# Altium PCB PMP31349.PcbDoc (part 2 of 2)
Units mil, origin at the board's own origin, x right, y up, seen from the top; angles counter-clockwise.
Board outline 2490.35 x 2400.55 mil, 4 copper layers (Top Layer, Internal Layer 1, Internal Layer 2, Bottom Layer), stack 73.068 mil thick; 110 components, 35 nets, 244 pads, 375 vias.
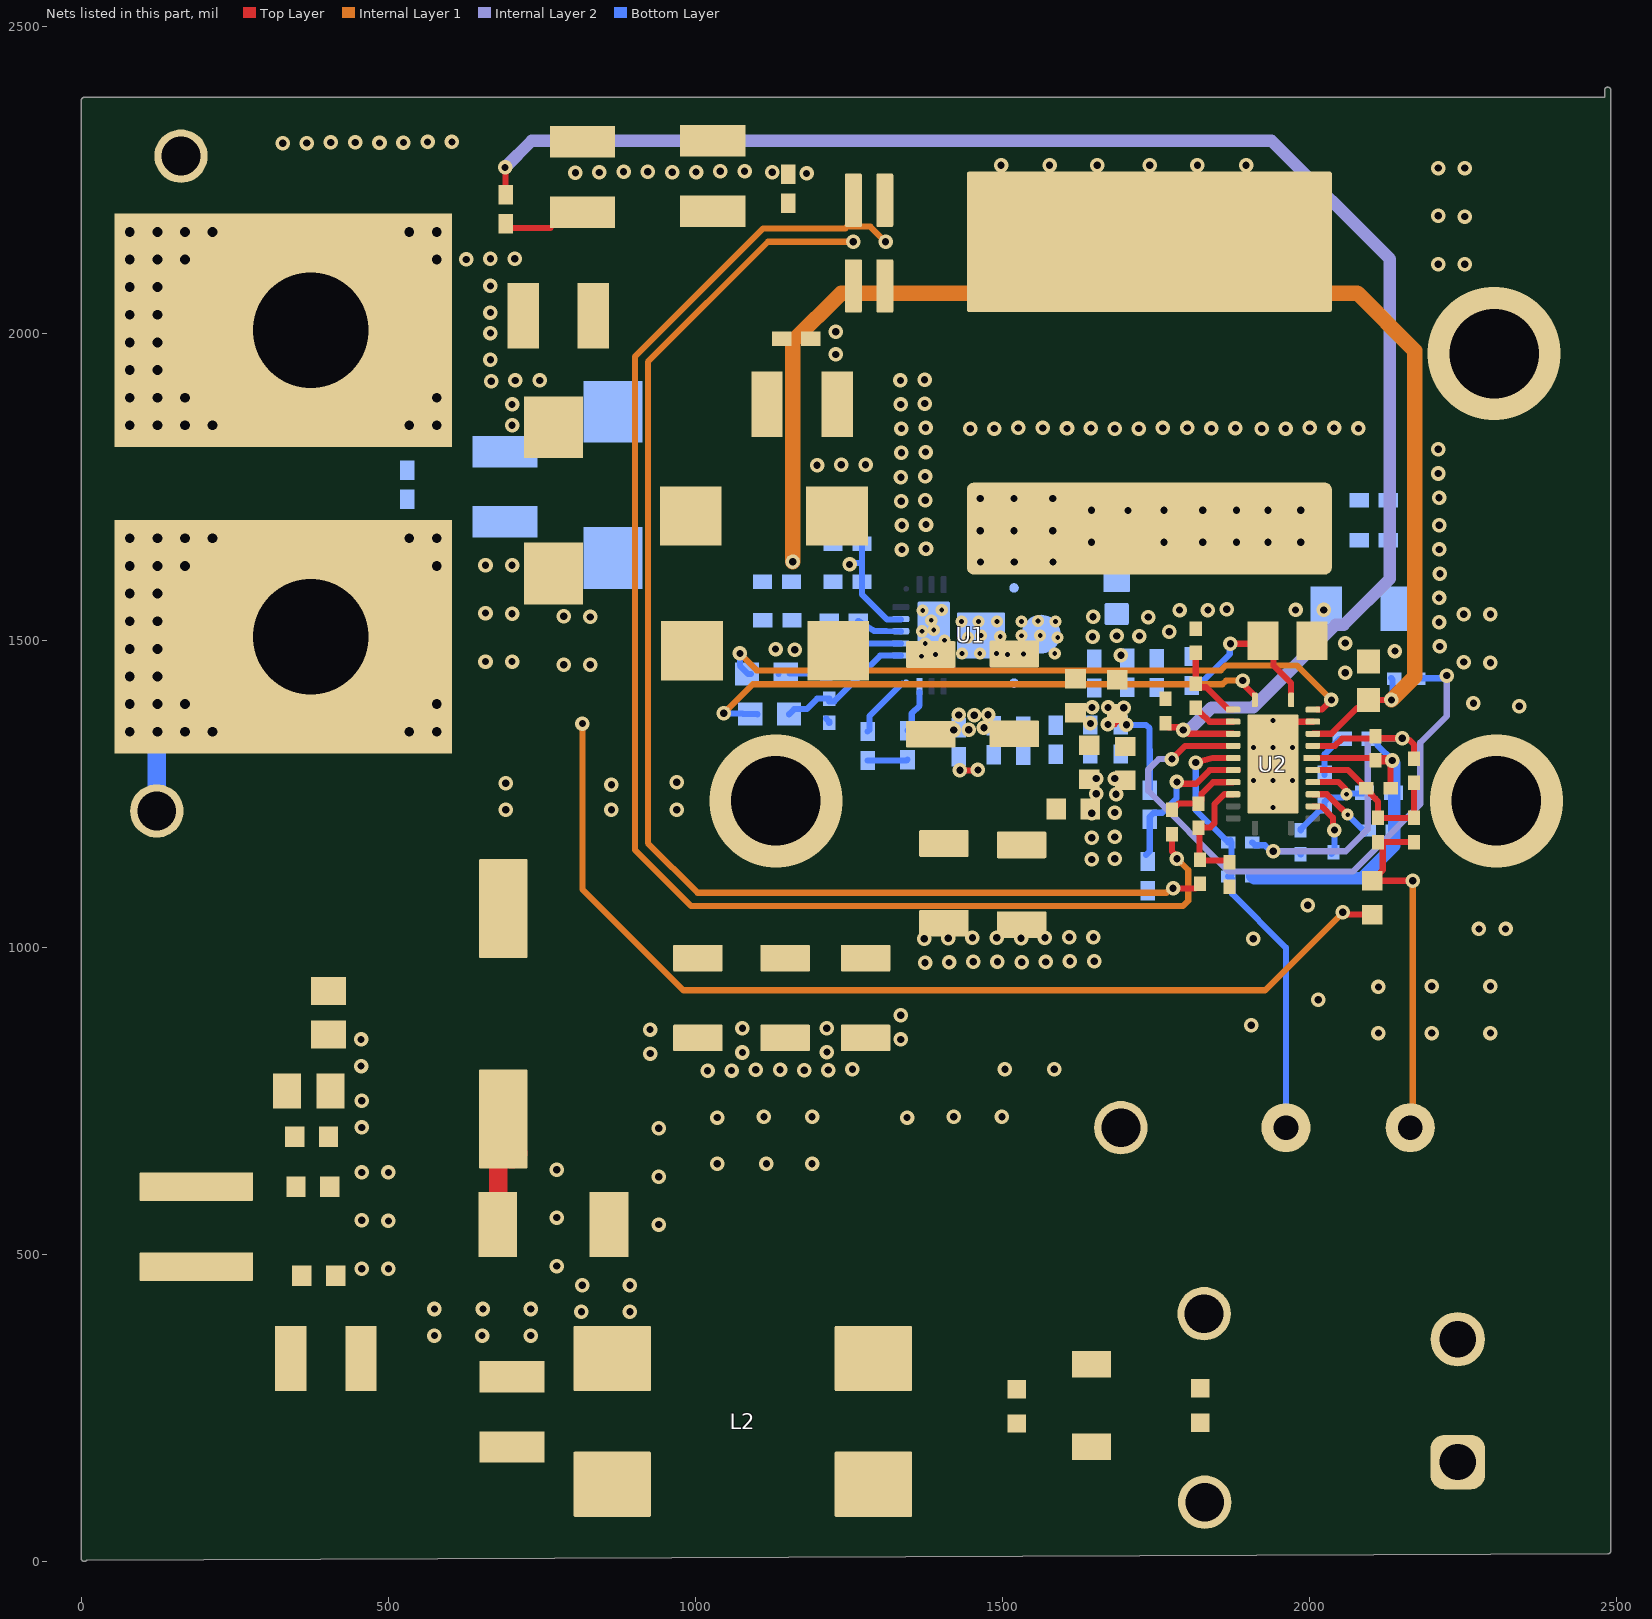
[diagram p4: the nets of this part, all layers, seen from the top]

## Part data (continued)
R22: library part CMP-0026403-2, "RES, 49.9 k, 1%, 0.063 W, AEC-Q200 Grade 0, 0402", Manufacturer=Vishay-Dale, Power_W=63mW, Supplier Part Number 1=541-49.9KLCT-ND, TempCo="100 ppm/C", Tolerance_%=1%, Value2=0.063W, Value_Code=49k9, ValueDisplayed=49.9k
R23: library part CMP-0025959-3, "RES, 10.2 k, 1%, 0.063 W, AEC-Q200 Grade 0, 0402", Manufacturer=Vishay-Dale, Power_W=63mW, Supplier Part Number 1=541-10.2KLCT-ND, TempCo="100 ppm/C", Tolerance_%=1%, Value2=0.063W, Value_Code=10k2, ValueDisplayed=10.2k
R24: library part CMP-0026225-2, "RES, 29.4 k, 1%, 0.063 W, AEC-Q200 Grade 0, 0402", Manufacturer=Vishay-Dale, Power_W=63mW, Supplier Part Number 1=541-29.4KLCT-ND, TempCo="100 ppm/C", Tolerance_%=1%, Value2=0.063W, Value_Code=29k4, ValueDisplayed=29.4k
R25: library part CMP-0026553-2, "RES, 7.15 k, 1%, 0.063 W, AEC-Q200 Grade 0, 0402", Manufacturer=Vishay-Dale, Power_W=63mW, Supplier Part Number 1=541-7.15KLCT-ND, TempCo="100 ppm/C", Tolerance_%=1%, Value2=0.063W, Value_Code=7k15, ValueDisplayed=DNP
U1: library part CMP-0120692-1, "100-V, 53-A GaN Half-Bridge Power Stage", Manufacturer="Texas Instruments", Max Supply Voltage=5.25V, Min Supply Voltage=4.75V, Nominal Supply Current=12mA, Operating Temperature Range="-40°C to +125°C"
U2: library part CMP-0049938-1, "Automotive, 80-V synchronous buck DC/DC controller with ultra-low IQ 24-VQFN -40 to 125", Digikey Part Number=296-LM5148QRGYRQ1CT-ND, Manufacturer="Texas Instruments", Max Supply Voltage=80V, Min Supply Voltage=3.5V, Mouser Part Number=595-LM5148QRGYRQ1, Nominal Supply Current=9.5-124uA, Operating Temperature Range="-40°C to +125°C", Output Voltage=3.3/5/12/0.8-55V, Switching Frequency=0.1-2.2MHz
Vin_Main VOUT: library part CMP-0055147-1, "Test Point, Multipurpose, Red, TH", Color=Red, Manufacturer=Keystone, PartNumber=5010, Supplier Part Number 1=36-5010-ND

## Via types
v1: diameter 23.62, hole 11.81, Top Layer to Bottom Layer, 274 vias
v2: diameter 32, hole 16, Top Layer to Bottom Layer, 56 vias
v3: diameter 19.68, hole 7.87, Top Layer to Bottom Layer, tented top, 26 vias
v4: diameter 19.68, hole 7.87, Top Layer to Bottom Layer, tented both sides, 11 vias
v5: diameter 23.62, hole 11.81, Top Layer to Bottom Layer, tented both sides, 5 vias
v6: diameter 216.54, hole 145.67, Top Layer to Bottom Layer, 3 vias

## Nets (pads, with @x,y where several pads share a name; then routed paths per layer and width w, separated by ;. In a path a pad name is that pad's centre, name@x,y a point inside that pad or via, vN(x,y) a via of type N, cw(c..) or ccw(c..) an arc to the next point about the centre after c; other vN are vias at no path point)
+Filter: C5.2 C6.2 C7.1 L1.2 L2.4
+Vin_Main: C2.1 C3.1 C4.1 J1.1 L2.1 Vin_Main.1
AGND1: C42.1 C56.2 C57.2 NT1.2 R18.2 R20.2 R24.2 R25.1 U2.7 | length 646.2
  Top Layer w10: U2.7@2005.53,1308.83 2107.23,1308.83 2107.23,1308.38 2109.02,1306.59 2112.07,1303.53 2126.21,1303.53 v1@2128.13,1301.62 ; R25.1@2131.92,1257.44 R25.1@2131.92,1259.62 v1@2131.92,1301.38
  Top Layer w15: C42.1@2107.23,1306.59 2109.02,1306.59 2130.37,1306.59 2132.21,1304.75 v1(2134.54,1304.75)
  Bottom Layer w10: C57.2@2100.31,1339.85 2104.25,1339.85 2111.06,1333.04 2111.06,1329.11 2134.54,1305.62 v1(2134.54,1304.75) v1@2137.15,1302.14
  Bottom Layer w20: R20.2@1906.7,1116.12 1910.09,1112.72 1953.69,1112.67 1977.25,1112.86 ; 1977.61,1112.49 2024.54,1112.86 2039.07,1112.86 2084.86,1112.86 2137.78,1165.77 2137.78,1252.58 2137.78,1300.53 2135.24,1303.08 v1@2135.73,1303.57
Bode: BODE.1 C55.1 R17.1 R21.2 | length 608
  Top Layer w10: R21.2@2111.71,1171.8 2119.25,1171.8 2138.74,1171.8 C55.1@2165.77,1171.8 ; R21.2@2119.25,1170.75 2119.25,1126.27 2113.63,1120.65 2113.63,1119.66 2102.88,1108.91 R17.1@2101.9,1108.91 2103.95,1108.91 v1(2168.05,1108.91) ; BODE.1@2154.81,716.23 ccw(c2164.12,716.23) BODE.1@2164.12,706.92
  Internal Layer 1 w10: BODE.1@2164.12,706.92 2168.05,710.86 v1(2168.05,1108.91)
CNFG: R24.1 U2.3 | length 102.8
  Top Layer w10: U2.3@2005.53,1230.09 2005.61,1230.01 2019.71,1230.01 2038.08,1211.64 2038.08,1194.14 v1(2040.69,1191.53)
  Bottom Layer w10: R24.1@2035.65,1152.23 2040.69,1157.27 v1(2040.69,1191.53)
COMP: C56.1 R19.1 R23.2 U2.5 | length 202.1
  Top Layer w10: U2.5@2005.53,1269.46 2047.44,1269.46 2058.48,1258.42 2058.48,1251.67 v3(2060.33,1249.82)
  Bottom Layer w10: R19.1@1985.68,1191.18 1985.68,1193.15 2015.6,1223.07 2017.73,1223.07 2024.54,1229.88 R23.2@2024.54,1233.82 2024.54,1237.75 2031.35,1244.56 2055.08,1244.56 2061.71,1251.2 2088.26,1251.2 C56.1@2089.64,1252.58
EN1: R4.1 R11.2 U2.19 | length 262.6
  Top Layer w10: v5(1784.2,1269.79) 1787.89,1269.79 1790.72,1266.96 1815.25,1266.96 1837.44,1289.14 U2.19@1883.44,1289.14
  Bottom Layer w10: R11.2@1733.97,1151.3 1739.82,1157.16 R4.1@1739.82,1203.13 ; R4.1@1739.82,1208.9 R4.1@1739.82,1203.13 ; v5(1784.2,1269.79) 1783.57,1269.16 1783.57,1242.98 1760.23,1219.64 1746.64,1219.64 1739.82,1212.83 R4.1@1739.82,1203.13
FB: C55.2 R21.1 R22.1 R25.2 U2.6 | length 274.2
  Top Layer w10: U2.6@2012.34,1289.07 2062.89,1289.07 2085.73,1266.22 2085.73,1262.28 2090.58,1257.44 2094.51,1257.44 2099.36,1252.6 2099.36,1250.63 2107.23,1242.75 2107.23,1242.26 2111.71,1237.78 R21.1@2111.71,1207.68 ; R21.1@2111.71,1211.17 2164.2,1211.17 C55.2@2169.86,1211.17 ; C55.2@2164.2,1209.15 2170.06,1215.01 R22.1@2170.06,1268.31
GND: C5.1 C6.1 C7.2 C8.2 C9.2 C10.2 C11.2 C12.2 C13.2 C14.2 C15.2 C16.2 C17.1 C18.1 C19.1 C20.1 C21.1 C22.1 C23.1 C24.2 C25.1 C26.1 C27.1 C28.2 C29.1 C30.1 C31.1 C32.1 C33.1 C34.1 C35.1 C36.1 C37.1 C38.2 C41.1 C43.2 C44.2 C45.2 C48.2 C49.2 C50.2 C51.2 C52.2 C53.2 C58.1 C59.2 C60.2 C61.2 C62.2 C63.2 C64.2 D1.2 GND.1 L2.3 NT1.1 R1.1 R8.2 R11.1 R15.1 TP7.1 U1.6 U1.15 U2.10 U2.25 | length 289.5
  Top Layer w10: v5(1430.8,1288.67) 1459.39,1288.67 ccw(c1459.39,1289.45) v1(1460.17,1289.45) ; v4(1940.57,1369.85) 1942.54,1367.88 U2.10@2005.53,1367.88
  Bottom Layer w10: C41.1@1213.28,1372.91 1218.12,1368.06 C41.1@1218.12,1366.1 ; v5(1251.09,1623.9) 1253.69,1626.51 1268.51,1626.51 1271.34,1629.34 ; C36.1@1271.34,1657.82 1271.34,1629.34 ; U1.15@1334.55,1534.56 1312.09,1534.56 1271.34,1575.31 C37.1@1271.34,1595.57 1271.34,1629.34
  other v1: 575.22,368.39 652.86,368.39 731.97,368.39 814.53,407.12 893.63,407.12 575.22,411.71 654.17,411.71 731.97,411.71 815.83,450.43 893.63,450.43 456.99,477.37 500.3,477.37 774.29,481.57 940.34,549.21 500.3,555.01 456.99,556.32 774.29,560.52 940.34,626.86 456.99,634.11 500.3,634.11 774.29,638.32 1035.59,648.28 1115.85,648.28 1190.04,648.28 940.34,705.96 456.99,707.33 1035.59,723.46 1344.81,723.46 1111.72,724.58 1190.04,724.58 1420.93,724.58 1499.26,724.58 456.99,750.65 1020.06,799.52 1058.98,799.98 1177.57,800.31 1098.38,801.11 1137.93,801.11 1216.49,800.77 1255.89,801.9 1504.21,801.9 1584.46,801.9 455.72,807.19 926.83,827.69 1076.73,829.33 1214.32,829.96 455.72,850.51 1334.51,850.51 2112.23,860.88 2198.94,860.88 2294.59,860.88 926.37,866.61 1076.73,868.88 1213.86,868.88 1905.06,873.81 1334.51,890.06 2014.15,915.37 2112.23,936.05 2198.94,937.18 2294.59,937.18 1374.15,975.53 1413.07,975.99 1531.66,976.32 1452.47,977.12 1492.02,977.12 1570.58,976.78 1609.98,977.91 1649.53,977.91 1372.84,1014.72 1411.76,1015.18 1530.35,1015.51 1908.58,1014.72 1451.17,1016.31 1490.71,1016.31 1569.27,1015.97 1608.68,1017.1 1648.22,1017.1 2275.84,1030.56 2319.15,1030.56 1997.34,1068.95 1645.37,1143.62 1682.9,1144.89 1645.37,1179.1 1682.9,1180.37 1645.37,1218.68 1682.9,1219.95 691.37,1224.38 863.47,1224.38 969.92,1224.38 1685.11,1249.82 863.47,1265.37 691.37,1267.7 969.92,1269.47 1682.9,1275.36 2341.7,1393.03 2267,1398 2058.24,1447.5 2294.59,1463.78 2251.28,1465.09 1692.99,1476.21 2139.06,1482.87 1161.93,1485.09 1130.7,1486.21 2212.04,1490.44 2058.24,1495.98 1646.87,1506.27 1686.06,1507.58 1723.12,1507.39 1771.5,1514.37 2210.91,1529.84 1737.43,1538.24 1647.57,1538.87 2251.28,1542.73 2294.59,1542.73 1788.46,1549.62 1834.57,1549.62 1977.25,1549.98 2023.36,1549.98 1865.1,1550.98 2210.91,1569.39 2212.35,1608.96 1336.43,1648.1 2211.22,1648.37 1375.62,1649.41 1336.43,1687.65 2211.22,1687.91 1375.62,1688.96 1335.3,1727.06 1374.49,1728.36 2210.91,1732.62 1334.84,1765.97 1374.03,1767.28 2209.78,1772.03 1198.28,1785.33 1237.68,1786.46 1277.23,1786.46 1335.64,1805.61 1374.83,1806.92 2209.78,1811.57 1335.64,1845.16 1447.68,1844.7 1486.6,1845.16 1605.19,1845.49 1682.9,1844.7 1721.82,1845.16 1840.41,1845.49 1922.2,1844.7 1961.12,1845.16 2079.71,1845.49 1374.83,1846.47 1526,1846.29 1565.55,1846.29 1644.11,1845.95 1761.22,1846.29 1800.77,1846.29 1879.33,1845.95 2000.52,1846.29 2040.07,1846.29 701.72,1850.46 701.72,1884.57 1334.51,1884.57 1373.7,1885.87 667.62,1922.36 707.02,1923.49 746.57,1923.49 1334.05,1923.49 1373.24,1924.79 666.44,1957.32 1228.79,1965.91 666.44,2000.63 1228.79,2002.64 666.44,2034.1 666.44,2077.42 2209.64,2112.64 2252.95,2112.64 627.04,2120.47 666.44,2121.6 705.99,2121.6 2252.95,2190.28 2209.64,2191.59 1181.13,2260.62 804.86,2261.66 843.78,2262.12 962.37,2262.45 1125.21,2262.4 883.18,2263.25 922.73,2263.25 1001.29,2262.91 1040.69,2264.04 1080.24,2264.04 2209.64,2269.39 2252.95,2269.39 1497.87,2274.09 1576.82,2274.09 1654.62,2274.09 1739.98,2274.09 1817.62,2274.09 1896.72,2274.09 328.32,2309.53 367.24,2309.99 485.83,2310.31 406.64,2311.12 446.19,2311.12 524.75,2310.77 564.15,2311.9 603.7,2311.9
  other v2: 79.15,1850.46 124.15,1850.46 169.15,1850.46 214.15,1850.46 534.15,1850.46 579.15,1850.46 79.15,1895.46 124.15,1895.46 169.15,1895.46 579.15,1895.46 79.15,1940.46 124.15,1940.46 79.15,1985.46 124.15,1985.46 79.15,2030.46 124.15,2030.46 79.15,2075.46 124.15,2075.46 79.15,2120.46 124.15,2120.46 169.15,2120.46 579.15,2120.46 79.15,2165.46 124.15,2165.46 169.15,2165.46 214.15,2165.46 534.15,2165.46 579.15,2165.46
  other v3: 1368.07,1474.57 1391.35,1477.33 1508.41,1477.14 1534.41,1478.14 1434.22,1478.98 1463.22,1478.98 1490.22,1478.98 1585.22,1478.98 1374.35,1495.33 1405.83,1500.44 1444.22,1504.98 1590,1504.98 1496.44,1506.49 1531.22,1507.99 1369.22,1515.12 1433.22,1530.98 1461.22,1530.98 1491.22,1530.98 1531.22,1530.98 1586.22,1530.98 1558.22,1531.98 1384.22,1532.98 1370.22,1548.98 1401.22,1549.98
  other v4: 1940.57,1228.12 1909.07,1272.22 1940.57,1272.22 1972.06,1272.22 1909.07,1325.76 1940.57,1325.76 1972.06,1325.76 1465.2,1508.31 1561.53,1508.31 1388.31,1517.17
  other v5: 1652.97,1250.66 1652.97,1275.36
  other v6: 1131.19,1238.83 2304.42,1238.83 2300.48,1967.18
GNDin: C2.2 C3.2 C4.2 GND_Main.1 J1.2 L2.2
HO: R5.1 U2.13 | length 953.8
  Top Layer w10: v1@1893.96,1427.13 1911.04,1410.05 U2.13@1911.04,1403.32
  Internal Layer 1 w10: v1(1046.22,1381.5) 1093.6,1428.88 1858.23,1428.88 1864.16,1434.81 v1(1891.36,1434.81)
  Bottom Layer w10: v1(1046.22,1381.5) 1077.07,1381.5 1078.11,1380.45 1101.09,1380.45 R5.1@1101.39,1380.15
ISNS: C54.2 R13.1 U2.20 | length 126
  Top Layer w10: R13.1@1776.11,1224.3 1776.11,1226.26 1780.96,1231.11 1783.22,1231.11 1786.81,1234.71 C54.2@1819.61,1234.71 1824.45,1239.55 1824.45,1250.88 1842.95,1269.38 1875.53,1269.38 U2.20@1875.61,1269.46
LO: R9.1 U2.11 | length 1074.5
  Top Layer w10: U2.11@2012.34,1387.57 2019.96,1387.57 v1(2035.71,1403.32)
  Internal Layer 1 w10: v1(1072.59,1478.98) 1100.04,1451.53 1121.98,1451.53 1855.6,1451.53 1863.57,1459.5 1979.53,1459.5 v1(2035.71,1403.32)
  Bottom Layer w10: v1(1072.59,1478.98) 1072.59,1459.14 1086.29,1445.44 R9.1@1090.63,1445.44
NetC1_1: C1.1 R1.2 | length 228.9
  Top Layer w10: C1.1@678.94,712.71 cw(c687.35,712.71) C1.1@687.35,721.12
  Top Layer w30: R1.2@678.94,558.69 C1.1@678.94,712.71
  Top Layer w50: C1.1@687.35,721.12 687.35,679.78 C1.1@701.72,665.41
NetC39_1: C39.1 R3.1 | length 65.5
  Bottom Layer w10: C39.1@1280.57,1304.73 1344.05,1304.73 R3.1@1345.5,1306.18
NetC39_2: C39.2 U1.11 | length 101.5
  Bottom Layer w10: C39.2@1280.57,1351.97 1283.52,1354.92 1283.52,1376.86 1336.84,1430.19
NetC40_1: C40.1 U2.15 | length 75.1
  Top Layer w10: C40.1@1812.1,1393.03 1812.1,1391.07 1819.61,1383.55 1821.58,1383.55 1837.25,1367.88 U2.15@1875.61,1367.88
NetC40_2: C40.2 R8.1 U2.14 | length 132.8
  Top Layer w10: C40.2@1811.56,1431.99 1819.61,1423.94 1831.84,1423.94 1868.21,1387.57 U2.14@1875.61,1387.57 ; C40.2@1814.77,1429.74 R8.1@1814.77,1480.11
NetC41_2: C41.2 R5.2 U1.12 | length 223.3
  Bottom Layer w10: R5.2@1152.57,1380.15 1160.83,1388.41 1181.4,1388.41 1198.46,1405.47 C41.2@1218.12,1405.47 ; C41.2@1218.12,1401.08 1226.33,1401.08 1300.76,1475.5 U1.12@1334.55,1475.5
NetC46_2: C46.2 C47.2 R15.2
NetC52_1: C52.1 R9.2 U1.13 | length 198.9
  Bottom Layer w10: R9.2@1135.54,1445.44 R9.2@1135.61,1445.52 ; R9.2@1153.54,1446.72 C52.1@1213.28,1446.72 ; C52.1@1216.44,1444.66 1266.98,1495.19 U1.13@1334.55,1495.19
NetC57_1: C57.1 R23.1 | length 72.9
  Bottom Layer w10: R23.1@2024.54,1281.06 2024.54,1315.27 2049.13,1339.85 C57.1@2053.07,1339.85
NetL3_2: L3.2 R7.1 R10.1 R13.2 | length 2374.1
  Top Layer w10: R13.2@1776.11,1184.93 1776.11,1156.67 1784.2,1148.58 v1(1784.2,1144.89)
  Internal Layer 1 w10: v1@1311.91,2147.17 1285.1,2173.97 1246.95,2173.97 1244.07,2171.1 1110.57,2171.1 901.67,1962.21 901.67,1159.23 993.29,1067.61 1793.83,1067.61 1802.63,1076.41 1802.63,1126.47 v1(1784.2,1144.89)
  other v1: 1309.79,2149.29
NetR2_1: R2.1 U1.14 | length 73.9
  Bottom Layer w10: R2.1@1265.27,1532.09 1276.02,1525.28 1290.7,1515.97 U1.14@1334.53,1514.86
NetR3_2: R3.2 U1.10 | length 71.2
  Bottom Layer w10: R3.2@1345.5,1353.42 1352.31,1360.23 1352.31,1381.41 1365.06,1394.16 U1.10@1365.06,1416.53
PFM/SYNC1: R16.2 R20.1 SYNC.1 U2.18 | length 721.6
  Top Layer w10: v1(1814.77,1301.38) 1842.34,1309.07 1846.52,1309.07 U2.18@1875.61,1308.83
  Bottom Layer w10: v1@1814.77,1301.07 1814.77,1224.06 R16.2@1867.33,1171.5 R16.2@1871.26,1175.42 ; R20.1@1867.33,1116.12 1869.3,1116.12 1874.14,1111.28 1874.14,1087.68 1961.71,1000.11 SYNC.1@1961.71,706.92 ; R20.1@1872.86,1118.09 1872.86,1157.52 R16.2@1872.86,1171.5
PG/SYNCOUT1: R12.1 U2.17 | length 1005.7
  Top Layer w10: v1(1776.11,1307.09) 1797.54,1328.51 U2.17@1875.61,1328.51
  Internal Layer 2 w10: v1(1776.11,1307.09) 1754.48,1307.09 1737.43,1290.03 1737.43,1255.19 1868.84,1123.78 2070.28,1123.78 2180.36,1233.86 2180.36,1333.98 2223.58,1377.19 v1(2223.58,1442.97)
  Bottom Layer w10: R12.1@2177.12,1437.78 2177.95,1438.61 2222.34,1438.61 v1@2223.16,1439.43
RT1: R18.1 U2.4 | length 115.3
  Top Layer w10: U2.4@2005.53,1249.77 U2.4@2005.53,1249.77 2028.25,1249.77 2050.92,1227.1 2051.48,1227.1 2062.05,1216.53 v3(2062.18,1216.53)
  Bottom Layer w10: v3(2062.18,1216.53) 2089.87,1188.85 2089.87,1186.3 2089.45,1185.88 R18.1@2086.9,1185.88
SW: C46.1 C47.1 D1.1 L3.1 U1.5 | length 769.9
  Top Layer w10: L3.1@1739.29,1682.36 cw(c1759.65,1682.36) L3.1@1759.65,1702.71 ; L3.1@1999.14,1702.71 L3.1@1981.32,1702.71 ; L3.1@1759.65,1702.71 L3.1@1876.99,1702.71 ; L3.1@1759.65,1702.71 L3.1@1821.87,1702.71 ; L3.1@1759.65,1702.71 L3.1@1981.32,1702.71 ; L3.1@1821.87,1702.71 L3.1@1981.32,1702.71 ; L3.1@1821.87,1702.71 L3.1@1876.99,1702.71 ; L3.1@1876.99,1702.71 L3.1@1981.32,1702.71
  other v1: 1464.29,1627.91 1519.41,1627.91 1582.4,1627.91 1645.13,1660.09 1763.24,1660.09 1826.23,1660.09 1881.35,1660.09 1932.53,1660.09 1985.68,1660.09 1463.87,1678.99 1518.99,1678.99 1581.98,1678.99 1704.57,1711.68 1645.13,1712.26 1763.24,1712.26 1826.23,1712.26 1881.35,1712.26 1932.53,1712.26 1985.68,1712.26 1463.87,1731.16 1518.99,1731.16 1581.98,1731.16
VCC: C34.2 C35.2 C36.2 C37.2 C43.1 R2.2 R12.2 U2.9 | length 2218.8
  Top Layer w10: U2.9@2005.53,1348.2 2005.61,1348.28 2035.71,1348.28 2077.82,1390.39 2096.08,1390.39 2109.01,1403.32 v1(2133.46,1403.32)
  Internal Layer 1 w25: v1(1158.66,1628.24) 1158.66,1986.62 1237.65,2065.61 2077.87,2065.61 2171.25,1972.23 2171.25,1441.1 v1(2133.46,1403.32)
  Bottom Layer w10: v1@2133.05,1399.78 2135.4,1402.13 2135.4,1436.63 R12.2@2133.05,1438.98
VCCX: C53.1 R6.2 U2.16 | length 2659.7
  Top Layer w10: v1(690.24,2270.33) 690.81,2269.77 690.81,2226.56 R6.2@691.37,2225.99 ; C53.1@1765.71,1365.79 1765.71,1363.82 1770.56,1358.98 1786.34,1358.98 1790.92,1354.4 v1(1794.6,1354.4) ; v1@1795.7,1355.5 1803.01,1348.2 U2.16@1875.61,1348.2
  Internal Layer 2 w20: v1(690.24,2270.33) 733.79,2313.88 1938.23,2313.88 2130.81,2121.29 2130.81,1600.7 2055.78,1525.67 2042.87,1525.67 1908.27,1391.06 1840.41,1391.06 1804.45,1355.1 1795.3,1355.1 v1(1794.6,1354.4)
VDDA: C42.2 R16.1 R19.2 R22.2 U2.8 | length 651.6
  Top Layer w10: v1(1940.8,1157.05) v1@1944.49,1157.05 ; U2.8@2012.34,1328.59 2041.3,1328.59 2053.24,1340.53 2103.4,1340.53 C42.2@2107.23,1344.36 ; C42.2@2107.23,1340.97 2151.09,1340.97 2153.71,1338.34 2162.81,1338.34 2170.11,1331.05 R22.2@2170.11,1306.8
  Internal Layer 2 w10: v1@1942.82,1157.05 2059.07,1157.05 2094.74,1192.72 2094.74,1335.09 2100.6,1340.95 v1(2151.11,1340.95)
  Bottom Layer w10: R16.1@1906.7,1171.5 1911.54,1166.65 1927.51,1166.65 1937.12,1157.05 v1(1940.8,1157.05) 1980.84,1157.05 1985.68,1152.21 R19.2@1985.68,1151.81
VIN: C1.2 C8.1 C9.1 C10.1 C11.1 C12.1 C13.1 C14.1 C15.1 C16.1 C17.2 C18.2 C19.2 C20.2 C21.2 C22.2 C23.2 C24.1 C25.2 C26.2 C27.2 C28.1 C29.2 C30.2 C31.2 C32.2 C33.2 C38.1 L1.1 R4.2 U1.7 U2.12 | length 441.9
  Top Layer w10: v1(1671.81,1363.43) 1682.53,1363.43 C12.1@1692.99,1373.89 ; v1(1871.26,1494.91) 1904.19,1494.91 1913.99,1504.72 C38.1@1913.99,1515.92 ; C38.1@1924.19,1499.79 1941.47,1482.51 1941.47,1459.36 1970.1,1430.73 U2.12@1970.1,1403.32
  Bottom Layer w10: v1(1701.98,1362.79) 1733.77,1362.79 1739.63,1356.93 1739.63,1322.5 1739.82,1322.3 R4.2@1739.82,1256.14 ; C31.2@1808.07,1426.75 1808.07,1428.92 1814.88,1435.73 1827.86,1435.73 1870.19,1478.06 1870.19,1493.85 v1(1871.26,1494.91)
  other v1: 1420.84,1354.4 1445.13,1354.69 1469.87,1358.16 1643.39,1365.19 1454.06,1378.41 1429.08,1378.85 1476.67,1379.2 1645.99,1391.06 1672.01,1391.2 1697.62,1390.8
VOUT: C44.1 C45.1 C48.1 C49.1 C50.1 C51.1 C59.1 C60.1 C61.1 C62.1 C63.1 C64.1 R6.1 R7.2 R10.2 R14.2 R17.2 VOUT.1 | length 4383.9
  Top Layer w10: R6.1@690.24,2171.91 764.18,2171.91 ; v1@1778.15,1096.43 v1(1777.95,1096.63) 1814.4,1096.63 1815.06,1097.29 1817.03,1097.29 1821.87,1102.14 R14.2@1821.87,1104.1 ; v1(2054.3,1057.73) ccw(c2058.24,1057.73) 2058.24,1053.8 R17.2@2101.9,1053.8
  Internal Layer 1 w10: v1(816.23,1364.82) 816.23,1095.17 980.74,930.66 1927.75,930.66 v1@2054.89,1057.8 ; v1(1257.17,2149.29) 1118.37,2149.29 922.73,1953.65 922.73,1170.28 1003.69,1089.31 1766.94,1089.31 1774.26,1096.63 v1(1777.95,1096.63)
  Bottom Layer w10: VOUT.1@123.32,1406.55 cw(c223.32,1406.55) 223.32,1506.55 VOUT.1@374.15,1506.55
  Bottom Layer w30: VOUT.1@123.32,1222.56 VOUT.1@123.32,1406.55
  other v1: 785.8,1460.65 829.11,1460.65 658.41,1465.79 701.72,1465.79 829.11,1538.45 785.8,1539.76 701.72,1543.59 658.41,1544.89 658.41,1622.54 701.72,1622.54
  other v2: 79.15,1351.55 124.15,1351.55 169.15,1351.55 214.15,1351.55 534.15,1351.55 579.15,1351.55 79.15,1396.55 124.15,1396.55 169.15,1396.55 579.15,1396.55 79.15,1441.55 124.15,1441.55 79.15,1486.55 124.15,1486.55 79.15,1531.55 124.15,1531.55 79.15,1576.55 124.15,1576.55 79.15,1621.55 124.15,1621.55 169.15,1621.55 579.15,1621.55 79.15,1666.55 124.15,1666.55 169.15,1666.55 214.15,1666.55 534.15,1666.55 579.15,1666.55
VOUTsns: C54.1 C58.2 R14.1 U2.21 | length 197.1
  Top Layer w10: C58.2@1869.03,1142.02 1823.33,1142.02 1820.74,1144.61 1820.74,1194.92 1819.96,1195.69 1838.59,1195.69 1845.25,1202.35 1845.25,1233.52 1861.51,1249.77 U2.21@1875.61,1249.77
pads on no net: U1.1 U1.2 U1.3 U1.4 U1.8 U1.9 U1.16 U2.1 U2.2 U2.22 U2.23 U2.24

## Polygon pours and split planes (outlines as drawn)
GND on Bottom Layer "GND_L04_P043" (solid, remove dead copper, pour order 43): 940.34,266.99 940.34,-76.13 -357,-76.13 -357,2396.32 2485.52,2396.32 2485.52,817.71 cw(c2484.33,817.7) 2484.33,816.51 2240.23,816.51 ccw(c2237.36,813.65) 2237.36,817.71 1961.71,817.71 1930.95,817.71 ccw(c1930.94,717.71) 1830.95,717.71 1830.95,683.34 cw(c1764.39,683.34) 1764.39,616.79 1463.03,616.79 1138.71,616.79 ccw(c1138.71,418.42) 940.34,418.42
VCC on Bottom Layer "VCC_L04_P016" (solid, remove dead copper, pour order 16): 1155.47,1674.79 ccw(c1155.47,1660.22) 1140.89,1660.22 1140.89,1518.11 ccw(c1150.04,1518.11) 1150.04,1508.97 1226.89,1508.97 ccw(c1226.89,1523.73) 1241.65,1523.73 1241.65,1645.98 ccw(c1217.87,1651.01) 1222.9,1674.79
SW on Bottom Layer "SW_L04_P011" (solid, remove dead copper, pour order 11): 1739.65,1633.63 ccw(c1739.65,1611.99) 1718.01,1611.99 1718.01,1594.8 cw(c1697.62,1594.8) 1697.62,1574.41 1443.15,1574.41 1442.76,1574.41 cw(c1442.76,1581.58) 1435.59,1581.58 1435.59,1744.55 cw(c1451.34,1744.55) 1451.34,1760.3 2081.26,1760.3 cw(c2081.26,1744.55) 2097.01,1744.55 2097.01,1642.19 cw(c2088.45,1642.19) 2088.45,1633.63
VOUT on Bottom Layer "VOUT_L04_P015" (solid, remove dead copper, pour order 15): 884.34,1746.11 cw(c884.34,1707.92) 922.53,1707.92 922.53,1355.75 cw(c893.89,1354.67) 894.97,1326.02 584.18,1326.02 570.56,1326.02 ccw(c570.56,1281.02) 525.56,1281.02 cw(c467.63,1281.02) 467.63,1223.09 -254.64,1223.09 cw(c-254.64,1246.71) -278.26,1246.71 -278.26,1656.16 cw(c-233.82,1656.16) -277.96,1661.32 cw(c-193.17,1661.32) -193.17,1746.11
NetC46_2 on Bottom Layer "NETC46_2_L04_P017" (solid, remove dead copper, pour order 17): 2154.81,1757.9 cw(c2154.81,1742.16) 2170.56,1742.16 2170.56,1514.12 cw(c2162.93,1513.55) 2162.69,1505.9 2115.44,1505.9 cw(c2115.44,1509.78) 2111.56,1509.78 2111.56,1746.71 cw(c2122.76,1746.71) 2122.76,1757.9
VIN on Bottom Layer "VIN_L04_P018" (solid, remove dead copper, pour order 18): 1819.15,1443.14 cw(c1819.15,1418.29) 1844.01,1418.29 1844.01,1364.52 cw(c1821.53,1364.52) 1821.53,1342.05 1777.9,1342.66 1466.77,1342.06 1415.67,1342.06 cw(c1415.55,1351.81) 1405.8,1351.68 1405.8,1377.62 cw(c1418.51,1377.62) 1418.51,1390.32 ccw(c1418.51,1413) 1441.18,1413 1441.18,1431.17 cw(c1453.15,1431.17) 1453.15,1443.14
GND on Top Layer "GND_L01_P046" (solid, remove dead copper, pour order 46): 1274.66,616.79 ccw(c1274.66,674.55) 1332.42,674.55 cw(c1358.39,674.55) 1358.39,700.52 1787.4,700.52 ccw(c1787.4,746.14) 1833.02,746.14 1833.02,746.73 cw(c1928.72,717.71) 1928.72,817.71 1959.48,817.71 2235.13,817.71 cw(c2235.13,813.65) 2238.01,816.51 2482.1,816.51 ccw(c2482.1,817.7) 2483.29,817.71 2483.29,2396.32 -359.23,2396.32 -359.23,-76.13 608.32,-76.13 608.32,232.59 903.71,232.59 ccw(c903.71,266.99) 938.11,266.99 938.11,418.42 cw(c1136.48,418.42) 1136.48,616.79
+Filter on Top Layer "+FILTER_L01_P042" (solid, remove dead copper, pour order 42): 25.29,447.48 cw(c88.39,447.48) 88.39,510.58 343.86,510.58 cw(c343.86,473.82) 380.62,473.82 380.62,297.5 ccw(c455.72,297.5) 455.72,222.39 897.4,222.39 cw(c897.4,179.45) 940.34,179.45 940.34,91.27 cw(c875.31,91.27) 875.31,26.24 125.29,26.24 cw(c125.29,126.24) 25.29,126.24
NetL3_2 on Top Layer "Top Layer-NetL3_2" (solid, remove dead copper, pour order 38): 1392.76,2249.75 ccw(c1411.1,2249.75) 1411.1,2231.41 1428.64,2231.41 1476.65,2231.2 2030.79,2231.2 cw(c2030.79,2215.21) 2046.78,2215.21 2046.78,2073.48 cw(c2031.77,2073.47) 2046.47,2070.47 2046.74,2070.48 2046.78,2070.48 2046.78,2055.07 2046.8,2019.55 2046.8,2006.89 cw(c2032.92,2007.84) 2033.31,1993.93 1451.66,1993.93 cw(c1451.66,2013.8) 1432.17,2009.93 ccw(c1413.74,2009.93) 1413.74,2028.36 1305.57,2028.36 cw(c1305.57,2042.63) 1291.29,2042.63 1291.49,2070.35 1291.49,2252.91 cw(c1303.25,2252.91) 1303.25,2264.67 1377.85,2264.67 cw(c1377.85,2249.75)
VIN on Top Layer "Top Layer-VIN" (solid, remove dead copper, pour order 22): 1364.22,1408.05 1357.34,1408.05 ccw(c1357.34,1308.05) 1257.34,1308.05 1257.34,1268.22 cw(c1157.34,1268.22) 1157.34,1168.22 1048.54,1168.22 584.18,1168.22 cw(c579.08,1220.03) 579.07,1167.97 146.66,1167.97 96.16,1167.97 ccw(c96.16,1097.1) 25.29,1097.1 25.29,644.87 ccw(c92.65,644.87) 92.65,577.51 355.34,577.51 ccw(c355.34,595.65) 373.47,595.65 373.47,793.69 ccw(c358.55,793.69) 358.55,808.61 cw(c358.55,815.5) 351.66,815.5 351.66,878.44 cw(c373.47,878.44) 373.47,900.25 1236.26,900.25 ccw(c1236.27,1000.25) 1336.26,1000.25 1336.26,1020.25 cw(c1408.3,1020.25) 1408.31,1092.29 1580.31,1092.29 ccw(c1580.31,1118.67) 1606.69,1118.67 1606.69,1212.67 1606.69,1290.68 cw(c1628.6,1290.68) 1628.6,1312.59 1641.46,1312.59 1704.57,1312.59 ccw(c1704.57,1331.14) 1723.12,1331.14 1723.12,1372.28 ccw(c1704.44,1372.29) 1722.76,1375.94 ccw(c1690.11,1376.16) 1690.32,1408.82 1684.17,1408.82 cw(c1683.4,1408.81) 1683.4,1408.05
GNDin on Top Layer "GNDIN_L01_P033" (solid, remove dead copper, pour order 33): 1214.06,404.19 cw(c1253.43,404.19) 1253.43,443.56 1381.09,443.56 ccw(c1381.09,467.32) 1404.85,467.32 cw(c1435.54,467.32) 1435.54,498.01 1492.02,498.01 2320.85,498.01 cw(c2320.85,453.99) 2364.88,453.99 2364.88,312.25 cw(c2317.63,312.25) 2317.63,265.01 1248.1,265.01 cw(c1248.1,299.05) 1214.06,299.05
+Vin_Main on Top Layer "+VIN_MAIN_L01_P026" (solid, remove dead copper, pour order 26): 1247.1,239.55 ccw(c1247.1,210.39) 1217.93,210.39 1217.93,36.71 ccw(c1248.1,36.71) 1248.1,6.55 2310.48,6.55 ccw(c2310.48,53.79) 2357.73,53.79 2357.73,195.52 ccw(c2313.71,195.52) 2313.71,239.55
VOUT on Top Layer "VOUT_L01_P013" (solid, remove dead copper, pour order 13): 971.55,1326.02 1100.11,1454.59 1099.69,1496.75 1099.69,1744.63 cw(c1121.45,1744.64) 1121.45,1766.39 ccw(c1121.45,1804.52) 1159.58,1804.53 1159.58,2009.93 cw(c1177.25,2009.93) 1177.25,2027.6 1257.89,2027.6 ccw(c1257.89,2042.63) 1272.92,2042.63 1272.92,2073.48 1272.92,2255.25 ccw(c1263.5,2255.25) 1263.5,2264.67 1238.2,2264.67 1227.94,2264.67 ccw(c1227.93,2246.17) 1209.44,2246.17 cw(c1194.23,2246.17) 1194.23,2230.96 1068.2,2230.96 776.86,2230.96 ccw(c776.86,2199.46) 745.36,2199.46 745.36,2144.35 ccw(c761.11,2144.35) 761.11,2128.6 cw(c761.11,2112.85) 776.86,2112.85 776.86,1998.44 774.2,1950.15 ccw(c792.61,1950.15) 792.61,1931.75 cw(c792.61,1890.41) 833.94,1890.41 833.94,1821.51 cw(c758.54,1821.51) 758.54,1746.11 666.44,1746.11 -193.17,1746.11 ccw(c-193.17,1661.32) -277.96,1661.32 ccw(c-233.88,1656.16) -278.26,1656.16 -278.26,1246.71 ccw(c-254.64,1246.71) -254.64,1223.09 531.31,1223.09 ccw(c531.31,1261.21) 569.43,1261.21 cw(c634.25,1261.21) 634.25,1326.02 638.68,1326.02
GND on Internal Layer 1 "GND_L02_P045" (solid, remove dead copper, pour order 45): 938.11,-76.13 -359.23,-76.13 -359.23,2396.32 2483.29,2396.32 2483.29,817.71 cw(c2482.1,817.7) 2482.1,816.51 2238.01,816.51 ccw(c2235.13,813.65) 2235.13,817.71 1959.48,817.71 1928.72,817.71 ccw(c1928.71,717.71) 1828.72,717.71 1828.72,683.34 cw(c1762.17,683.34) 1762.16,616.79 1460.8,616.79 1136.48,616.79 ccw(c1136.48,418.42) 938.11,418.42
GND on Internal Layer 2 "GND_L03_P044" (solid, remove dead copper, pour order 44): 940.34,266.99 940.34,-76.13 -357,-76.13 -357,2396.32 2485.52,2396.32 2485.52,817.71 cw(c2484.33,817.7) 2484.33,816.51 2240.23,816.51 ccw(c2237.36,813.65) 2237.36,817.71 1961.71,817.71 1930.95,817.71 ccw(c1930.94,717.71) 1830.95,717.71 1830.95,683.34 cw(c1764.39,683.34) 1764.39,616.79 1463.03,616.79 1138.71,616.79 ccw(c1138.71,418.42) 940.34,418.42

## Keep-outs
Keep-Out Layer:
  text ".Layer_Name" at -351.15,-1088.81 h60

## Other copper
Top Layer:
  pour cut-out: 603.7,1310.54 603.7,1180.02 583.57,1180.02 ccw(c585.44,1177.71) 588.42,1177.71 588.42,1297.36
  pour cut-out: 1398.64,1804.53 2096.08,1804.53 2096.08,1571.3 1398.64,1571.3
  pour cut-out: 1234.4,1641.01 1239.62,1641.01 1268.37,1641.01 1268.37,1606.8 1234.16,1606.8
  text ".Layer_Name" at -429.89,-1088.81 h60
Internal Layer 1:
  pour cut-out: 1407.1,1789.5 1415.07,1789.5 2076.66,1789.5 2076.66,1585.29 2068.79,1585.29 1407.1,1585.29
Internal Layer 2:
  pour cut-out: 1760.77,1585.48 1745.6,1570.31 1406.83,1570.31 1406.83,1581.1 1406.83,1789.69 2076.39,1789.69 2076.39,1585.48 2068.52,1585.48
Bottom Layer:
  pour cut-out: 2190.92,1764.93 2189.14,1498.84 2173.29,1498.84 ccw(c2173.29,1501.35) 2175.8,1501.35 2175.8,1764.93
  pour cut-out: 1705.58,1564.17 1773.46,1564.17 1802.9,1593.61 2091.55,1593.61 2111.56,1613.63 2111.56,1628.24 1752.25,1628.24 1736.84,1628.24
  pour cut-out: 1431.47,1611.79 1391.35,1611.79 1391.35,1796 1416.86,1821.51 2134.33,1821.51 2190.92,1764.93 1434.17,1764.93
  pour cut-out: 1241.65,1679.55 1241.65,1530.24 1312.56,1530.24 1319.48,1537.16 1319.48,1679.55
  pour cut-out: 1335.91,1538.05 1335.91,1534.09 1349.98,1520.02 1353.72,1520.02 1353.72,1547.89 1354.65,1548.82
  pour cut-out: 1403.47,1612.2 1403.88,1611.79 1433.22,1611.79 1433.22,1567.66 1434.8,1566.08 1433.82,1565.1 1408.14,1565.1
  text ".Layer_Name" at -351.15,-1088.81 h60

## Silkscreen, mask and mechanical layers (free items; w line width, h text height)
Top Overlay:
  lines w4: 1592.84,1199.92 1630.07,1099 ; 1776.87,1131.28 1808,1178 ; 2112.23,1275.36 2178.88,1328.43 ; 2175.81,1189.13 2245.82,1140.21
  lines w15: 926.46,2396.32 926.95,1016.41 2397.25,1016.84 2398.91,2396.32
  text "(35x37)mm" at 2369.28,2095.23 h30 r90
  text "'.PRJ_Number'.PCB_Rev" at 57.57,49.86 h108.27
  text ".Layer_Name" at -351.15,-1088.81 h60
Bottom Overlay:
  circle w9.84: c1341.46,1623.62 r4.92
  lines w5.91: 1309.96,1412.01 1309.96,1402.16 1319.81,1402.16 ; 1309.96,1599.02 1309.96,1608.86 1319.81,1608.86 ; 1605.24,1402.16 1615.08,1402.16 1615.08,1412.01 ; 1605.24,1608.86 1615.08,1608.86 1615.08,1599.02
  lines w15: 926.46,2396.32 926.95,1016.41 2397.24,1018.36 2398.91,2396.32
  text "Output: 12V, 20A max" at 105.29,143.36 h50 r270
  text ".Layer_Name" at -351.15,-1088.81 h60
Top Paste:
  text ".Layer_Name" at -351.15,-1088.81 h60
Bottom Paste:
  drawing of 7 lines, arcs and shapes, not listed
  text ".Layer_Name" at -351.15,-1088.81 h60
Top Solder:
  text ".Layer_Name" at -351.15,-1088.81 h60
  text ".Layer_Name" at -351.15,-1088.81 h60
Bottom Solder:
  text ".Layer_Name" at -351.15,-1088.81 h60
Drill Guide:
  text ".Layer_Name" at -351.15,-1088.81 h60
M1 Board Outline:
  lines w10: 5.2,5.77 5.2,2379.45 2485.52,2379.45 ; 5.2,7.63 2485.52,17.97 2485.52,2380.57
  text ".Layer_Name" at -429.89,-1088.81 h60
M2 Board Dimensions:
  rectangle: -803.15,-630.32 -428.15,-505.32
  rectangle: -928.15,-505.32 -803.15,-380.32
  lines w7: -928.15,-505.32 71.85,-505.32 ; -803.15,-630.32 -803.15,-380.32 ; -678.15,-630.32 -678.15,-380.32 ; -428.15,-630.32 -428.15,-380.32 ; -178.15,-630.32 -178.15,-380.32 ; -928.15,-630.32 -928.15,-380.32 71.85,-380.32 71.85,-630.32 -928.15,-630.32
  text ".Layer_Name" at -429.89,-1088.81 h60
M3 3D STEP Top:
  text ".Layer_Name" at -429.89,-1088.81 h60
M4 3D STEP Bottom:
  text ".Layer_Name" at -429.89,-1088.81 h60
M5 Assembly Top:
  lines w10: -1239.83,-1160.49 4610.2,-1160.49 ; -1239.83,-957.15 4610.2,-957.15 ; -1239.83,-753.82 -1239.83,-1363.82 2765.17,-1363.82 ; 336.17,-1363.82 -1239.33,-1363.82 -1239.33,-753.82 4610.2,-753.82 4610.2,-1363.82 2288.79,-1363.82 ; 1044.06,-1363.82 1044.06,-753.82 ; 2074.84,-957.15 2074.84,-753.82 ; 2796.73,-957.15 2796.73,-753.82 ; 3300.62,-1370.32 3300.62,-1167.49
  text ".Designator" at 1462.52,1505.51 h19.68 r90
  text "COMPONENTS MARKED 'DNP' SHOULD NOT BE POPULATED." at 103.3,-548.82 h60
  text "ASSEMBLY VARIANT:" at 102.8,-664.32 h60
  text ".VariantName" at 1130.93,-664.32 h60
  text "PCB VIEWED FROM TOP SIDE" at -1196.02,-885.99 h60
  text "BOARD #:" at 1087.57,-885.99 h60
  text ".PRJ_Number" at 1546.45,-885.99 h60
  text "REV:" at 2233.47,-885.99 h60
  text ".PCB_Rev" at 2465.92,-885.99 h60
  text "SVN REV:" at 2866.75,-885.99 h60
  text ".VersionControl_RevNumber" at 3360.94,-885.99 h60
  text "TID #:" at 1087.57,-1089.32 h60
  text ".TID" at 1546.45,-1089.32 h60
  text "PLOT NAME =" at -1196.02,-1294.66 h60
  text ".plot_File_Name" at -429.89,-1294.66 h60
  text "GENERATED    :" at 1089.57,-1294.66 h60
  text ".Print_Date" at 1813.4,-1294.66 h60
  text ".Print_Time" at 2404.6,-1294.66 h60
  text "TEXAS INSTRUMENTS" at 3472.25,-1294.66 h60
M6 Assembly Bottom:
  lines w10: -1240.33,-957.65 4610.2,-957.65 ; -1238.33,-1160.99 4610.2,-1160.99 ; 84.99,-1370.82 84.99,-1167.99 ; 628.25,-957.65 628.25,-754.32 ; 1116.51,-1364.32 4610.2,-1364.32 3151.81,-1364.32 ; 1356.67,-1364.32 -1240.33,-1364.32 -1240.33,-754.32 4610.2,-754.32 ; 1369.82,-957.65 1369.82,-754.32 ; 2400.6,-1364.32 2400.6,-754.32 ; 4609.2,-1364.32 4609.2,-754.32 ; 4609.7,-1364.32 4609.7,-754.32
  text "COMPONENTS MARKED 'DNP' SHOULD NOT BE POPULATED." at 4776.21,-548.32 h60
  text ".VariantName" at 3436.94,-664.32 h60
  text "ASSEMBLY VARIANT:" at 4436.57,-664.32 h60
  text ".VersionControl_RevNumber" at 107.35,-886.49 h60
  text "SVN REV:" at 593.67,-886.49 h60
  text ".PCB_Rev" at 998.43,-886.49 h60
  text "REV:" at 1238.75,-886.49 h60
  text ".PRJ_Number" at 1839.16,-886.49 h60
  text "BOARD #:" at 2305.92,-886.49 h60
  text "PCB VIEWED FROM BOTTOM SIDE" at 4565.88,-886.49 h60
  text ".TID" at 1858.84,-1089.82 h60
  text "TID #:" at 2305.92,-1089.82 h60
  text "TEXAS INSTRUMENTS" at -82.7,-1295.16 h60
  text ".Print_Time" at 1099.12,-1295.16 h60
  text ".Print_Date" at 1717.88,-1295.16 h60
  text "GENERATED    :" at 2500.77,-1295.16 h60
  text ".plot_File_Name" at 3898.18,-1295.16 h60
  text "PLOT NAME =" at 4565.88,-1295.16 h60
M9 Title Sheet:
  drawing of 55 lines, arcs and shapes, not listed
  text "1" at -267.31,5101.18 h70
  text "2" at 2090.7,5101.18 h70
  text "3" at 4467.35,5101.18 h70
  text "4" at 6842.7,5101.18 h70
  text "A" at -1364.65,4211.18 h70
  text "A" at 7930.35,4211.18 h70
  text "B" at -1364.65,2335.18 h70
  text "B" at 7930.35,2335.18 h70
  text "C" at -1364.65,459.18 h70
  text "C" at 7930.35,459.18 h70
  text "PROJECT TITLE:" at 4895.35,-652.82 h45
  text ".PRJ_Title" at 4945.35,-786.15 h70
  text "DESIGNED FOR:" at 4895.35,-953.82 h45
  text ".PRJ_Customer" at 4945.35,-1093.82 h70
  text "FILE NAME:" at 4895.35,-1253.82 h45
  text ".PCB_File_Name_No_Path" at 4945.35,-1373.82 h70
  text "D" at -1364.65,-1412.82 h70
  text "D" at 7930.35,-1412.82 h70
  text "Texas Instruments (TI) and/or its licensors do not warrant the accuracy or completeness of this specification" at 35.85,-1535.66 h45
  text "ENGINEER:" at 4895.35,-1543.82 h45
  text "LAYOUT BY:" at 6400.35,-1543.82 h45
  text "or any information contained therein. TI and/or its licensors do not warrant that this design will meet" at -9.14,-1648.32 h45
  text ".PRJ_Engineer" at 4945.35,-1698.81 h70
  text ".PCB_Layout" at 6450.85,-1698.81 h70
  text "the specifications, will be suitable for your application or fit for any particular purpose, or will operate in" at -9.14,-1760.99 h45
  text "ALTIUM DESIGNER VERSION:" at 6400.35,-1853.82 h45
  text "an implementation. TI and/or its licensors do not warrant that the design is production worthy. You should" at -9.14,-1873.66 h45
  text "completely validate and test your design implementation to confirm the system functionality for your application." at 35.85,-1986.32 h40
  text ".print_Scale" at 4945.35,-1987.15 h70
  text ".Application_BuildNumber" at 6450.85,-1987.15 h70
  text "1" at -267.31,-2198.82 h70
  text "2" at 2090.7,-2198.82 h70
  text "3" at 4467.35,-2198.82 h70
  text "4" at 6842.7,-2198.82 h70
M10 Fab Notes:
  drawing of 189 lines, arcs and shapes, not listed
  text "DESIGN INFORMATION" at 5931.37,4931.35 h60
  text "MIN. TRACK WIDTH:" at 5286.81,4799.23 h60
  text "10" at 6383.05,4799.23 h60
  text "MIL" at 6537.81,4799.23 h60
  text "7.874" at 6212.18,4679.96 h60
  text "MIN. CLEARANCE:" at 5286.81,4675.1 h60
  text "MIL" at 6537.81,4675.1 h60
  text "MIN. VIA PAD SIZE:" at 5286.81,4550.98 h60
  text "24" at 6353.06,4550.98 h60
  text "MIL" at 6537.81,4550.98 h60
  text "0.05mm (2MIL)" at 5981.81,4421.08 h60
  text "MINIMUM ANNULAR RING" at 4957.58,4412.85 h60
  text "EXTERNAL" at 6689.81,4412.85 h60
  text "PER" at 5157.58,4302.73 h60
  text "IPC-D-275 CLASS 2 LEVEL C" at 5377.58,4302.72 h60
  text "MIL, HOLES" at 6865.81,4202.25 h60
  text "+/-" at 6473.35,4193.66 h60
  text "+/-" at 7327.35,4193.66 h60
  text "REGISTRATION TOLERANCES:" at 4957.58,4192.6 h60
  text "METAL" at 6157.35,4192.6 h60
  text "5" at 6733.55,4192.6 h60
  text "3" at 7566.55,4192.6 h60
  text "MIL" at 7682.81,4192.6 h60
  text "HOLE SIZE TOLERANCE (UNLESS OTHERWISE SPECIFIED):" at 4957.58,4094.28 h60
  text "+/-" at 7327.35,4091.41 h60
  text "3" at 7566.55,4090.35 h60
  text "MIL" at 7682.81,4090.35 h60
  text "MATERIAL:" at 4882.81,3952.7 h60
  text "FR-4 High Tg" at 5869.25,3824.17 h60
  text "X" at 5724.81,3816.19 h60
  text "FR-4" at 5303.81,3811.67 h60
  text "OTHER" at 6791.81,3811.67 h60
  text "62 MIL (1.6mm) +/-10%" at 5623.91,3668.64 h60
  text "X" at 5503.81,3666.19 h60
  text "THICKNESS:" at 4957.58,3660.42 h60
  text "OTHER" at 6908.81,3660.42 h60
  text "TOLERANCE:" at 4957.58,3522.1 h60
  text "X" at 5805.81,3522.1 h60
  text "ANSI IPC-6012 TYPE 3 CLASS 2" at 5983.83,3522.1 h60
  text "OTHER +/-" at 5983.81,3377.91 h60
  text "BOW & TWIST:" at 4957.58,3232.72 h60
  text "X" at 5805.81,3232.72 h60
  text "ANSI IPC-6012 TYPE 3 CLASS 2" at 5983.83,3232.72 h60
  text "OTHER +/-" at 5983.81,3086.03 h60
  text "DRILLING:" at 4882.81,2955.41 h60
  text "NC_DRILL FILES" at 6643.81,2850.22 h60
  text "REFERENCE:" at 4957.58,2846.28 h60
  text "X" at 5614.81,2846.19 h60
  text "AS SHOWN" at 5792.81,2846.28 h60
  text "X" at 6515.81,2846.28 h60
  text "OTHER" at 6941.81,2704.03 h60
  text "PTH COPPER THICKNESS:" at 4957.26,2700.5 h60
  text "X" at 6096.49,2700.5 h60
  text "20-30 um" at 6224.49,2700.5 h60
  text "BOARD FINISH:" at 4882.81,2552.9 h60
  text "SILKSCREEN:" at 5038.03,2442.78 h60
  text "X" at 5995.81,2442.78 h60
  text "TOP" at 6112.81,2442.78 h60
  text "X" at 6505.81,2442.78 h60
  text "BOTTOM" at 6623.81,2442.78 h60
  text "SILKSCREEN COLOR:" at 5038.03,2287.59 h60
  text "X" at 5994.81,2287.59 h60
  text "WHITE" at 6112.81,2287.59 h60
  text "OTHER" at 6623.81,2287.59 h60
  text "X" at 6125.81,2144.14 h60
  text "GREEN" at 6243.81,2144.14 h60
  text "OTHER" at 6861.81,2144.14 h60
  text "SOLDER RESIST COLOR:" at 5038.03,2137.27 h60
  text "X" at 6125.81,1989.89 h60
  text "MATTE" at 6243.81,1989.89 h60
  text "SEMI-GLOSS" at 6861.35,1989.25 h60
  text "IMMERSION GOLD (ENIG)" at 5943.81,1817.12 h60
  text "ENEPIG" at 7281.35,1809.9 h60
  text "SURFACE FINISH:" at 4882.81,1808.9 h60
  text "X" at 5765.81,1808.9 h60
  text "IMM. TIN/SILVER OR EQUIV" at 5212.35,1671.58 h60
  text "OTHER" at 6643.81,1667.64 h60
  text "ARRAY/PANEL:" at 4882.81,1512.27 h60
  text "CUT AND TRIM PER M1 BOARD OUTLINE" at 5943.81,1504.04 h60
  text "N.C. ROUTE" at 5943.81,1368.08 h60
  text "X" at 6631.81,1368.08 h60
  text "V. SCORE" at 6809.81,1368.08 h60
  text "CERTIFICATION:" at 4882.81,1238.95 h60
  text "MATERIALS AND WORKMANSHIP FOR ALL PCBS" at 5607.81,1238.95 h60
  text "TO MEET OR EXCEED THE REQUIREMENTS OF:" at 5607.81,1144.89 h60
  text "X" at 5245.32,1016.26 h60
  text "ANSI IPC-A-600F CLASS ->" at 5373.31,1016.26 h60
  text "X" at 7021.32,1016.26 h60
  text "2" at 7131.31,1016.26 h60
  text "1" at 6816.31,1014.76 h60
  text "3" at 7485.31,1014.76 h60
  text "X" at 6057.32,868.57 h60
  text "RoHS" at 6185.31,868.57 h60
  text "OTHER" at 6829.71,868.57 h60
  text "PER ORDER" at 7226.77,868.57 h60
  text "ALL BOARDS MUST MEET OR EXCEED UL94-V0 REQUIREMENTS." at 4910.35,714.75 h60
  text "PCB MUST BEAR THE UL94V-0 UL REGISTERED MATERIAL ID NUMBER" at 4910.35,598.68 h60
  text "ADDITIONAL REQUIREMENTS:" at 4882.81,429.26 h60
  text "MICROSECTION:" at 4957.58,322.13 h60
  text "YES" at 5863.31,322.13 h60
  text "REQUIRED" at 6724.81,177.8 h60
  text "BARE BOARD ELEC. TEST:" at 4957.58,174.94 h60
  text "NONE" at 6263.31,174.94 h60
  text "X" at 6606.81,174.94 h60
  text "PER ORDER" at 7316.81,174.94 h60
  text "XX MIL VIAS REQUIRE NON-CONDUCTIVE FILL AND PLANARIZE" at 5125.73,-30 h59
  text "XX MIL VIAS REQUIRE CONDUCTIVE FILL AND PLANARIZE" at 5133.73,-133.98 h60
  text "OUTER XX MIL TRACES REQUIRE 50 OHM SINGLE-ENDED IMPEDANCE" at 5132.74,-297.36 h58
  text "LAYER 2 & 3 (INNER LAYERS) XX MIL WIDE, XX MIL SPACE / TRACES REQUIRE 100 OHM DIFFERENTIAL IMPEDANCE" at 5124.74,-533.08 h60
  text ".Layer_Name" at -429.89,-1088.81 h60
M11 Gerber Information:
  lines w10: -1239.83,-1160.49 4610.2,-1160.49 ; -1239.83,-957.15 4610.2,-957.15 ; -1239.83,-753.82 -1239.83,-1363.82 2765.17,-1363.82 ; 336.17,-1363.82 -1239.33,-1363.82 -1239.33,-753.82 4610.2,-753.82 4610.2,-1363.82 2288.79,-1363.82 ; 1044.06,-1363.82 1044.06,-753.82 ; 2074.84,-957.15 2074.84,-753.82 ; 2796.73,-957.15 2796.73,-753.82 ; 3300.62,-1370.32 3300.62,-1167.49
  text "ALL ARTWORK VIEWED FROM TOP SIDE" at -1196.02,-885.99 h60
  text "BOARD #:" at 1087.57,-885.99 h60
  text ".PRJ_Number" at 1546.45,-885.99 h60
  text "REV:" at 2233.47,-885.99 h60
  text ".PCB_Rev" at 2465.92,-885.99 h60
  text "SVN REV:" at 2866.75,-885.99 h60
  text ".VersionControl_RevNumber" at 3360.94,-885.99 h60
  text "LAYER NAME =" at -1196.02,-1088.81 h60
  text "TID #:" at 1087.57,-1089.32 h60
  text ".TID" at 1546.45,-1089.32 h60
  text "PLOT NAME =" at -1196.02,-1294.66 h60
  text ".plot_File_Name" at -429.89,-1294.66 h60
  text "GENERATED    :" at 1089.57,-1294.66 h60
  text ".Print_Date" at 1813.4,-1294.66 h60
  text ".Print_Time" at 2404.6,-1294.66 h60
  text "TEXAS INSTRUMENTS" at 3472.25,-1294.66 h60
M12 Stackup:
  drawing of 295 lines, arcs and shapes, not listed
  text "Layer" at 169.85,4759.18 h60
  text "Name" at 579.76,4759.18 h60
  text "Material" at 1629.47,4759.18 h60
  text "Thickness" at 2489.24,4759.18 h60
  text "Constant" at 3139.07,4759.18 h60
  text "Board Layer Stack" at 3708.93,4759.18 h60
  text "Top Overlay" at 579.76,4639.18 h60
  text "Top Solder" at 579.76,4519.18 h60
  text "Solder Resist" at 1629.47,4519.18 h60
  text "0.40mil" at 2489.24,4519.18 h60
  text "3.5" at 3139.07,4519.18 h60
  text "1" at 169.85,4399.18 h60
  text "Top Layer" at 579.76,4399.18 h60
  text "2.76mil" at 2489.24,4399.18 h60
  text "Dielectric 1" at 579.76,4279.18 h60
  text "PP-006" at 1629.47,4279.18 h60
  text "2.80mil" at 2489.24,4279.18 h60
  text "4.1" at 3139.07,4279.18 h60
  text "2" at 169.85,4159.18 h60
  text "Internal Layer 1" at 579.76,4159.18 h60
  text "CF-004" at 1629.47,4159.18 h60
  text "1.38mil" at 2489.24,4159.18 h60
  text "Dielectric1" at 579.76,4039.18 h60
  text "FR-4 High Tg" at 1629.47,4039.18 h60
  text "59.20mil" at 2489.24,4039.18 h60
  text "4.8" at 3139.07,4039.18 h60
  text "3" at 169.85,3919.18 h60
  text "Internal Layer 2" at 579.76,3919.18 h60
  text "CF-004" at 1629.47,3919.18 h60
  text "1.38mil" at 2489.24,3919.18 h60
  text "Dielectric 2" at 579.76,3799.18 h60
  text "PP-006" at 1629.47,3799.18 h60
  text "2.80mil" at 2489.24,3799.18 h60
  text "4.1" at 3139.07,3799.18 h60
  text "4" at 169.85,3679.18 h60
  text "Bottom Layer" at 579.76,3679.18 h60
  text "2.76mil" at 2489.24,3679.18 h60
  text "Bottom Solder" at 579.76,3559.18 h60
  text "Solder Resist" at 1629.47,3559.18 h60
  text "0.40mil" at 2489.24,3559.18 h60
  text "3.5" at 3139.07,3559.18 h60
  text "Bottom Overlay" at 579.76,3439.18 h60
  text ".Layer_Name" at -429.89,-1088.81 h60
M13 Component Bodies Top:
  text ".Layer_Name" at -429.89,-1088.81 h60
M14 Component Bodies Bottom:
  text ".Layer_Name" at -429.89,-1088.81 h60
M15 Courtyards Top:
  text ".Layer_Name" at -429.89,-1088.81 h60
M16 Courtyards Bottom:
  text ".Layer_Name" at -429.89,-1088.81 h60
Drill Drawing:
  circle w10: c1608.18,2869.7 r27.67
  circle w10: c1608.18,2745.2 r16.6
  circle w10: c1608.18,2745.2 r27.67
  lines w10: 1580.51,2606.86 1594.34,2606.86 1594.34,2593.03 1622.01,2593.03 1622.01,2606.86 1635.84,2606.86 1635.84,2634.53 1622.01,2634.53 1622.01,2648.36 1594.34,2648.36 1594.34,2634.53 1580.51,2634.53 1580.51,2606.86 ; 1580.51,2966.53 1635.84,2966.53 1635.84,3021.86 1580.51,3021.86 1580.51,2966.53 ; 1580.51,3146.36 1635.84,3146.36 1608.18,3091.03 1580.51,3146.36 ; 1580.51,3215.53 1608.18,3229.36 1635.84,3215.53 1622.01,3243.2 1635.84,3270.86 1608.18,3257.03 1580.51,3270.86 1594.34,3243.2 1580.51,3215.53 ; 1580.51,3340.03 1580.51,3353.86 1594.34,3367.7 1580.51,3381.53 1580.51,3395.36 1594.34,3395.36 1608.18,3381.53 1622.01,3395.36 1635.84,3395.36 1635.84,3381.53 1622.01,3367.7 1635.84,3353.86 1635.84,3340.03 1622.01,3340.03 1608.18,3353.86 1594.34,3340.03 1580.51,3340.03 ; 1580.51,3478.36 1594.34,3478.36 1608.18,3464.53 1622.01,3478.36 1635.84,3478.36 1622.01,3492.2 1635.84,3506.03 1622.01,3506.03 1608.18,3519.86 1594.34,3506.03 1580.51,3506.03 1594.34,3492.2 1580.51,3478.36
  lines w12: 1530.35,2555.68 4762.54,2555.68 ; 1530.35,3551.68 4762.54,3551.68 ; 1868.36,2431.18 1868.36,3676.18 ; 2200.52,2431.18 2200.52,3676.18 ; 2837,2431.18 2837,3676.18 ; 3096.2,2431.18 3096.2,3676.18 ; 3471.44,2431.18 3471.44,3676.18 ; 4195.99,2431.18 4195.99,3676.18 ; 1530.35,2431.18 4762.54,2431.18 4762.54,3676.18 1530.35,3676.18 1530.35,2431.18
  text "Symbol" at 1605.05,3589.03 h72
  text "Quantity" at 1905.71,3589.03 h72
  text "Finished Hole Size" at 2237.87,3589.03 h72
  text "Plated" at 2874.35,3589.03 h72
  text "Hole Type" at 3133.55,3589.03 h72
  text "Drill Layer Pair" at 3508.79,3589.03 h72
  text "Hole Tolerance" at 4233.34,3589.03 h72
  text "37" at 1905.71,3464.53 h60
  text "7.87mil (0.200mm)" at 2237.87,3464.53 h60
  text "PTH" at 2874.35,3464.53 h60
  text "Round" at 3133.55,3464.53 h60
  text "Top Layer - Bottom Layer" at 3508.79,3464.53 h60
  text "279" at 1905.71,3340.03 h60
  text "11.81mil (0.300mm)" at 2237.87,3340.03 h60
  text "PTH" at 2874.35,3340.03 h60
  text "Round" at 3133.55,3340.03 h60
  text "Top Layer - Bottom Layer" at 3508.79,3340.03 h60
  text "56" at 1905.71,3215.53 h60
  text "16.00mil (0.406mm)" at 2237.87,3215.53 h60
  text "PTH" at 2874.35,3215.53 h60
  text "Round" at 3133.55,3215.53 h60
  text "Top Layer - Bottom Layer" at 3508.79,3215.53 h60
  text "2" at 1905.71,3091.03 h60
  text "40.00mil (1.016mm)" at 2237.87,3091.03 h60
  text "PTH" at 2874.35,3091.03 h60
  text "Round" at 3133.55,3091.03 h60
  text "Top Layer - Bottom Layer" at 3508.79,3091.03 h60
  text "2" at 1905.71,2966.53 h60
  text "59.06mil (1.500mm)" at 2237.87,2966.53 h60
  text "PTH" at 2874.35,2966.53 h60
  text "Round" at 3133.55,2966.53 h60
  text "Top Layer - Bottom Layer" at 3508.79,2966.53 h60
  text "5" at 1905.71,2842.03 h60
  text "63.00mil (1.600mm)" at 2237.87,2842.03 h60
  text "PTH" at 2874.35,2842.03 h60
  text "Round" at 3133.55,2842.03 h60
  text "Top Layer - Bottom Layer" at 3508.79,2842.03 h60
  text "3" at 1905.71,2717.53 h60
  text "145.67mil (3.700mm)" at 2237.87,2717.53 h60
  text "PTH" at 2874.35,2717.53 h60
  text "Round" at 3133.55,2717.53 h60
  text "Top Layer - Bottom Layer" at 3508.79,2717.53 h60
  text "2" at 1905.71,2593.03 h60
  text "188.00mil (4.775mm)" at 2237.87,2593.03 h60
  text "PTH" at 2874.35,2593.03 h60
  text "Round" at 3133.55,2593.03 h60
  text "Top Layer - Bottom Layer" at 3508.79,2593.03 h60
  text "386 Total" at 1905.71,2468.53 h60
  text ".Layer_Name" at -429.89,-1088.81 h60
M17 Embedded Cavity:
  text ".Layer_Name" at -429.89,-1088.81 h60
M18 Embedded Assembly:
  text ".Layer_Name" at -429.89,-1088.81 h60
M19 Embedded Keepout:
  text ".Layer_Name" at -425.95,-1092.75 h60

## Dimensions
5.2,7.63 to 5.2,2379.45 on M2 Board Dimensions
5.2,5.77 to 2485.54,12.95 on M2 Board Dimensions
-928.15,-630.32 to 71.85,-630.32 on M2 Board Dimensions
